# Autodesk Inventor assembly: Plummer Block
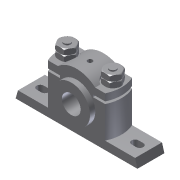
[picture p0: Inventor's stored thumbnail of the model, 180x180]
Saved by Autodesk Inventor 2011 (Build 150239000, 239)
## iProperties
Created: 2009-04
Part Number: Plummer Block
Document SubType Name: Assembly
Designer: Sham
Author: Sham
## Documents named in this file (7)
- C:\Users\CADSoft\Desktop\part files\c13-inv-2011-prt\c13-tut01-inv\Plummer Block.iam
- C:\Inventor_2011\c09_inv_2011_02062010\Plummer Block\Casting1.ipt
- C:\Users\CADSoft\Desktop\part files\c13-inv-2011-prt\c13-tut01-inv\Cap.ipt
- C:\Users\CADSoft\Desktop\part files\c13-inv-2011-prt\c13-tut01-inv\Brasses.ipt
- C:\Users\CADSoft\Desktop\part files\c13-inv-2011-prt\c13-tut01-inv\Bolt.ipt
- C:\Users\CADSoft\Desktop\part files\c13-inv-2011-prt\c13-tut01-inv\Nut.ipt
- C:\Users\CADSoft\Desktop\part files\c13-inv-2011-prt\c13-tut01-inv\Lock Nut.ipt
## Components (9 placed, 6 different names)
1. Casting:1 — Insert:1, Flush:1, Insert:2, Mate:1, Insert:3, Insert:4
2. Cap:1 — Insert:1, Flush:1, Insert:5, Insert:6
3. Brasses:1 — Insert:2, Mate:1
4. Bolt:1 — Insert:3
5. Bolt:2 — Insert:4
6. Nut:1 — Insert:6, Insert:7
7. Nut:2 — Insert:5, Insert:8
8. Lock Nut:1 — Insert:7
9. Lock Nut:2 — Insert:8
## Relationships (10: Insert 8, Flush 1, Mate 1)
- Insert:1: Casting:1 ↔ Cap:1
- Flush:1: Casting:1 ↔ Cap:1
- Insert:2: Casting:1 ↔ Brasses:1
- Mate:1: Casting:1 ↔ Brasses:1
- Insert:3: Casting:1 ↔ Bolt:1
- Insert:4: Casting:1 ↔ Bolt:2
- Insert:5: Cap:1 ↔ Nut:2
- Insert:6: Cap:1 ↔ Nut:1
- Insert:7: Nut:1 ↔ Lock Nut:1
- Insert:8: Nut:2 ↔ Lock Nut:2
